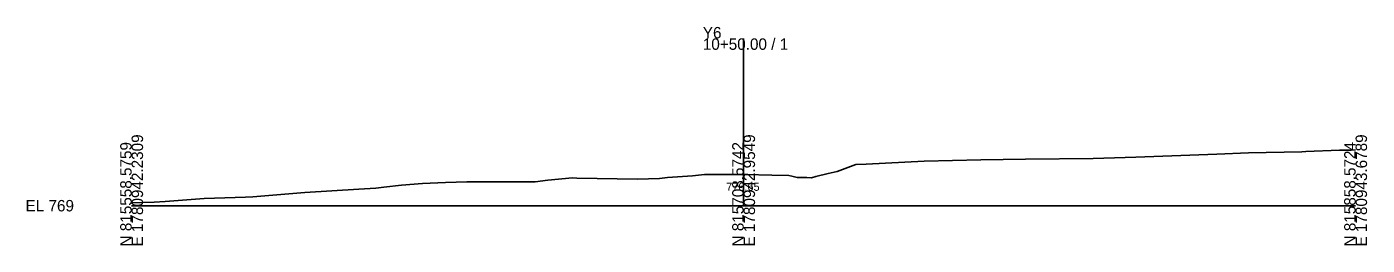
# Model space of a CAD drawing. Extents: x -26 to 1603, y -10 to 6024.
# Drawn here: x -25.7 to 302.8, y 490.3 to 543.9 of the extents above; entities that cross this region are included whole.
import ezdxf

# ---------------------------------------------------------------- set-up
doc = ezdxf.new("R2010")
doc.units = 0
for name, color, linetype in [('Exist Cross Section Cell', 7, 'Continuous'), ('Exist XS Center Line Elevation Label', 7, 'Continuous'), ('Exist XS Ground Line', 7, 'Continuous')]:
    doc.layers.add(name, color=color, linetype=linetype)

msp = doc.modelspace()

# ---------------------------------------------------------------- linework, layer by layer
at = {"layer": 'Exist Cross Section Cell'}
for p, q in [((150, 500), (150, 541.03)), ((0, 500), (150, 500)), ((150, 500), (300, 500))]:
    msp.add_line(p, q, dxfattribs=at)
at = {"layer": 'Exist XS Ground Line'}
for p, q in [((246.1, 511.92), (265.97, 512.62)), ((265.97, 512.62), (273.71, 512.93)), ((273.71, 512.93), (286.85, 513.22)), ((286.85, 513.22), (287.83, 513.25)), ((287.83, 513.25), (296.02, 513.59)), ((296.02, 513.59), (298.91, 513.65)), ((298.91, 513.65), (300, 513.68)), ((172.89, 508.42), (177.52, 510.07)), ((177.52, 510.07), (180.04, 510.15)), ((180.04, 510.15), (194.28, 510.92)), ((194.28, 510.92), (208.14, 511.24)), ((208.14, 511.24), (219.06, 511.4)), ((219.06, 511.4), (235.68, 511.59)), ((235.68, 511.59), (246.1, 511.92)), ((98.87, 505.88), (102.01, 506.22)), ((102.01, 506.22), (108.09, 506.81)), ((108.09, 506.81), (109.14, 506.75)), ((109.14, 506.75), (123.98, 506.49)), ((123.98, 506.49), (129.41, 506.63)), ((129.41, 506.63), (131.37, 506.88)), ((131.37, 506.88), (137.5, 507.35)), ((137.5, 507.35), (140.42, 507.62)), ((140.42, 507.62), (143.97, 507.63)), ((143.97, 507.63), (150, 507.65)), ((150, 507.65), (150.43, 507.65)), ((150.43, 507.65), (156.92, 507.51)), ((156.92, 507.51), (161.08, 507.43)), ((161.08, 507.43), (161.83, 507.25)), ((161.83, 507.25), (163.11, 506.94)), ((163.11, 506.94), (165.46, 506.88)), ((165.46, 506.88), (166.64, 506.83)), ((166.64, 506.83), (167.69, 507.18)), ((167.69, 507.18), (170.73, 507.86)), ((170.73, 507.86), (172.89, 508.42)), ((29.7, 502.18), (42.47, 503.21)), ((42.47, 503.21), (55.68, 504.08)), ((55.68, 504.08), (59.84, 504.3)), ((59.84, 504.3), (61.78, 504.55)), ((61.78, 504.55), (66.18, 505.03)), ((66.18, 505.03), (71.26, 505.44)), ((71.26, 505.44), (76.94, 505.71)), ((76.94, 505.71), (82.12, 505.83)), ((82.12, 505.83), (98.87, 505.88)), ((0, 500.72), (5.53, 500.9)), ((5.53, 500.9), (8.19, 500.99)), ((8.19, 500.99), (17.78, 501.77)), ((17.78, 501.77), (27.95, 502.07)), ((27.95, 502.07), (29.7, 502.18))]:
    msp.add_line(p, q, dxfattribs=at)

# ---------------------------------------------------------------- texts
at = {"layer": 'Exist Cross Section Cell'}
for s, p in [('Y6', (140, 541.03)), ('10+50.00 / 1', (140, 538.23)), ('EL 769', (-26, 498.6))]:
    msp.add_text(s, height=2.8, dxfattribs=at).set_placement(p)
for s, p in [('E 1780942.2309', (2.8, 490)), ('E 1780942.9549', (152.8, 490)), ('E 1780943.6789', (302.8, 490)), ('N 815558.5759', (0, 490)), ('N 815708.5742', (150, 490)), ('N 815858.5724', (300, 490))]:
    msp.add_text(s, height=2.8, rotation=90, dxfattribs=at).set_placement(p)
at = {"layer": 'Exist XS Center Line Elevation Label'}
msp.add_text('776.65', height=2, dxfattribs=at).set_placement((145.74, 503.65))

doc.saveas('drawing.dxf')
